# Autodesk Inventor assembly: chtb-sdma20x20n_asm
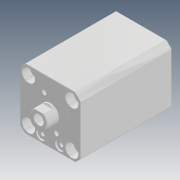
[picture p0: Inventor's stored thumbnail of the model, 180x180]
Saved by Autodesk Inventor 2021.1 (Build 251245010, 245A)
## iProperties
Created: 2018-05
Part Number: chtb-sdma20x20n_asm
Description: STEP AP214
Document SubType Name: Assembly
Designer: user
Title: chtb-sdma20x20n_asm.STEP
Revision Number: ÈÎºÎ
Sending System: SolidWorks 2016
Preprocessor: SwSTEP 2.0
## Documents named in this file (5)
- D:\Vault_2016\Projekty\Clamptek\Hydraulic\CHTB\CHTB-20\Inventor\CHTB-SDMA20x20N\chtb-sdma20x20n_asm.iam
- D:\Vault_2016\Projekty\Clamptek\Hydraulic\CHTB\CHTB-20\Inventor\CHTB-SDMA20x20N\CHTB-SDMA20X20NBT.ipt
- D:\Vault_2016\Projekty\Clamptek\Hydraulic\CHTB\CHTB-20\Inventor\CHTB-SDMA20x20N\CHTB-SDMA20X20NHSG.ipt
- D:\Vault_2016\Projekty\Clamptek\Hydraulic\CHTB\CHTB-20\Inventor\CHTB-SDMA20x20N\QG_3.ipt
- D:\Vault_2016\Projekty\Clamptek\Hydraulic\CHTB\CHTB-20\Inventor\CHTB-SDMA20x20N\socket set screw flat point_iso_ISO 4026 - M5 x 5-N.ipt
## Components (5 placed, 5 different names)
1. CHTB-SDMA20X20NBT_1
2. CHTB-SDMA20X20NHSG_2
3. QG_3_3
4. socket set screw flat point_iso_ISO 4026 - M5 x 5-N_4
5. socket set screw flat point_iso_ISO 4026 - M5 x 5-N_5
